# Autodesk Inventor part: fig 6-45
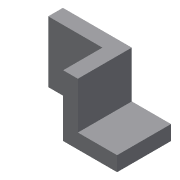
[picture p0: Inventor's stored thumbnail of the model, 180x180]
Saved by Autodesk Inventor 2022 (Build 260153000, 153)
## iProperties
Created: 2001-12
Part Number: fig 6-45
Document SubType Name: Modeling
Designer: Renu Muthoo
Density: 1 g/cm^3
Material: Generic
Appearance: Default
Control State: 0
Master: False
Checked Out: False
Shininess: 77.0
Angle Display Precision: 2
Document Length Units: 11269
Document Angle Units: 11279
Document Time Units: 11290
Document Mass Units: 11283
Document Length Units Precision: 3
Document Angle Units Precision: 2
Density: 0.0
Volumn: 0.0
Area: 0.0
PropertySet Name: Model Information
Author: Renu Muthoo
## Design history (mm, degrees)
node "Sketch1"
sketch "Sketch2"
  geometry: L1 (16.794, 27.142)-(16.794, -22.858); L2 (16.794, -22.858)-(-27.206, -22.858); L3 (-27.206, -22.858)-(-27.206, -10.858); L4 (-27.206, -10.858)-(4.794, -10.858); L5 (4.794, -10.858)-(4.794, 27.142); L6 (4.794, 27.142)-(16.794, 27.142)
  constraints: 12 end point, 4 parallel, 2 perpendicular, 1 vertical
  dimensions: "d0" = 44 distance of L1.end L2.end; "d1" = 50 distance of L1.start L1.end; "d2" = 12 distance of L2.end L3.end
extrude "Extrusion1" new body sketch "Sketch2" distance "d3" = 44; taper "d4" = 0 deg
sketch "Sketch4"
  geometry: L1 (-16.794, -27.142)-(-16.794, 22.858) reference; L2 (27.206, 22.858)-(27.206, 10.858) reference; L3 (-16.794, -27.142)-(-61.001, -27.142); L4 (-61.001, -27.142)-(-61.001, 22.858); L5 (-61.001, 22.858)-(-16.794, 22.858)
  constraints: 6 end point, 2 perpendicular, 1 parallel
extrude "Extrusion3" join sketch "Sketch4" distance "d13" = 12; taper "d14" = 0 deg
body "Solid1"
